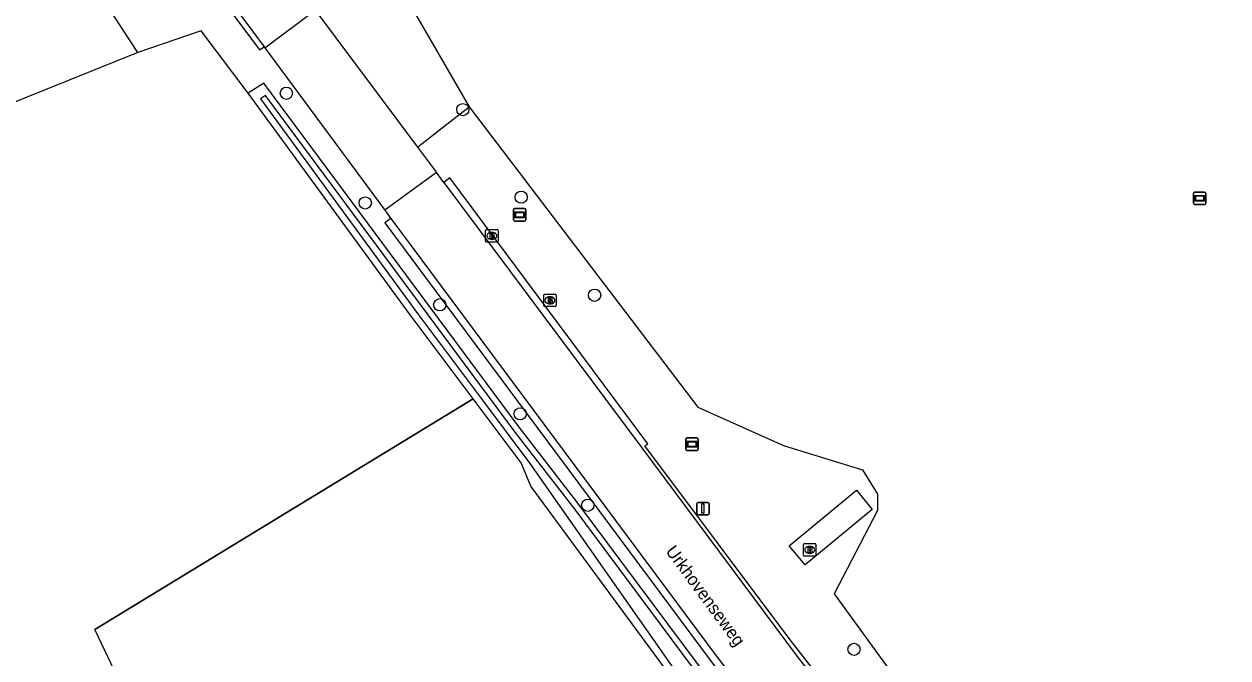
# Model space of a CAD drawing. Extents: x 164494 to 166241, y 382475 to 384494.
# Drawn here: x 165055.3 to 165151.8, y 383082.1 to 383132.9 of the extents above; entities that cross this region are included whole.
import ezdxf

# ---------------------------------------------------------------- set-up
doc = ezdxf.new("R2010")
doc.units = 0
for name, color, linetype in [('IMGEO_Berm_halfverhard', 7, 'Continuous'), ('IMGEO_Boom', 7, 'Continuous'), ('IMGEO_Bouwland', 7, 'Continuous'), ('IMGEO_Brandkraan', 7, 'Continuous'), ('IMGEO_Erf', 7, 'Continuous'), ('IMGEO_Grasland_agrarisch', 7, 'Continuous'), ('IMGEO_Grasland_overig', 7, 'Continuous'), ('IMGEO_Groenvoorziening', 7, 'Continuous'), ('IMGEO_Hek', 7, 'Continuous'), ('IMGEO_Loofbos', 7, 'Continuous'), ('IMGEO_Openbare_ruimte_label', 7, 'Continuous'), ('IMGEO_Rijbaan_lokaal_gesloten', 7, 'Continuous'), ('IMGEO_Verkeersbordpaal', 7, 'Continuous'), ('IMGEO_Verklikker', 7, 'Continuous'), ('IMGEO_Voetpad_open', 7, 'Continuous'), ('IMGEO_Waterloop', 7, 'Continuous')]:
    doc.layers.add(name, color=color, linetype=linetype)

msp = doc.modelspace()

# ---------------------------------------------------------------- linework, layer by layer
at = {"layer": 'IMGEO_Berm_halfverhard'}
for points in [[(165010.162, 383216.934), (165012.663, 383213.574), (165041.519, 383174.67), (165059.934, 383149.875), (165074.189, 383130.821), (165074.54, 383131.069)], [(165132.015, 383063.951), (165116.709, 383083.512), (165105.08, 383099.084), (165105.321, 383099.248), (165089.441, 383120.561), (165088.96, 383120.2)], [(165084.718, 383117.313), (165084.231, 383116.963), (165110.383, 383081.771), (165114.948, 383075.929), (165121.14, 383068.038), (165127.167, 383060.515), (165131.174, 383055.545)]]:
    msp.add_lwpolyline(points, dxfattribs=at)
at = {"layer": 'IMGEO_Boom'}
for centre in [(165076.331, 383127.349), (165090.474, 383126.038), (165082.657, 383118.554), (165095.156, 383119.022), (165101.044, 383111.15), (165088.626, 383110.392), (165095.079, 383101.648), (165100.493, 383094.313), (165121.84, 383082.758)]:
    msp.add_circle(centre, 0.489, dxfattribs=at)
at = {"layer": 'IMGEO_Bouwland'}
msp.add_lwpolyline([(165074.123, 383155.419), (165090.977, 383126.271)], dxfattribs=at)
at = {"layer": 'IMGEO_Brandkraan'}
for p, q in [((165092.307, 383115.49), (165092.307, 383116.342)), ((165092.382, 383116.416), (165093.234, 383116.416)), ((165092.795, 383116.196), (165092.82, 383116.196)), ((165093.308, 383116.342), (165093.308, 383115.49)), ((165093.234, 383115.416), (165092.382, 383115.416)), ((165092.818, 383115.636), (165092.793, 383115.636)), ((165097.035, 383111.246), (165097.887, 383111.246)), ((165096.96, 383110.32), (165096.96, 383111.172)), ((165097.887, 383110.246), (165097.035, 383110.246)), ((165097.471, 383110.466), (165097.446, 383110.466)), ((165097.448, 383111.026), (165097.473, 383111.026)), ((165097.961, 383111.172), (165097.961, 383110.32)), ((165117.788, 383090.307), (165117.788, 383091.159)), ((165117.863, 383091.233), (165118.715, 383091.233)), ((165118.276, 383091.013), (165118.301, 383091.013)), ((165118.789, 383091.159), (165118.789, 383090.307)), ((165118.715, 383090.233), (165117.863, 383090.233)), ((165118.299, 383090.453), (165118.274, 383090.453))]:
    msp.add_line(p, q, dxfattribs=at)
for points in [[(165092.307, 383115.49), (165092.307, 383116.342)], [(165092.382, 383116.416), (165093.234, 383116.416)], [(165092.655, 383116.116), (165092.655, 383115.716), (165092.868, 383115.716)], [(165092.886, 383116.116), (165092.655, 383116.116)], [(165092.834, 383116.035), (165092.78, 383116.035), (165092.78, 383115.959)], [(165093.308, 383116.342), (165093.308, 383115.49)], [(165093.234, 383115.416), (165092.382, 383115.416)], [(165092.78, 383115.959), (165092.833, 383115.959)], [(165092.842, 383115.883), (165092.78, 383115.883), (165092.78, 383115.802)], [(165092.78, 383115.802), (165092.842, 383115.802)], [(165097.035, 383111.246), (165097.887, 383111.246)], [(165096.96, 383110.32), (165096.96, 383111.172)], [(165097.887, 383110.246), (165097.035, 383110.246)], [(165097.308, 383110.946), (165097.308, 383110.546), (165097.521, 383110.546)], [(165097.539, 383110.946), (165097.308, 383110.946)], [(165097.487, 383110.865), (165097.433, 383110.865), (165097.433, 383110.789)], [(165097.433, 383110.789), (165097.486, 383110.789)], [(165097.495, 383110.713), (165097.433, 383110.713), (165097.433, 383110.632)], [(165097.433, 383110.632), (165097.495, 383110.632)], [(165097.961, 383111.172), (165097.961, 383110.32)], [(165117.788, 383090.307), (165117.788, 383091.159)], [(165117.863, 383091.233), (165118.715, 383091.233)], [(165118.136, 383090.933), (165118.136, 383090.533), (165118.349, 383090.533)], [(165118.367, 383090.933), (165118.136, 383090.933)], [(165118.789, 383091.159), (165118.789, 383090.307)], [(165118.715, 383090.233), (165117.863, 383090.233)], [(165118.315, 383090.852), (165118.261, 383090.852), (165118.261, 383090.776)], [(165118.261, 383090.776), (165118.314, 383090.776)], [(165118.323, 383090.7), (165118.261, 383090.7), (165118.261, 383090.619)], [(165118.261, 383090.619), (165118.323, 383090.619)]]:
    msp.add_lwpolyline(points, dxfattribs=at)
for centre, radius, start, end in [((165092.384, 383116.34), 0.0765, 91.55205, 178.44795), ((165092.384, 383116.34), 0.0765, 91.55205, 178.44795), ((165092.835, 383115.997), 0.0379, 267.82845, 90.93552), ((165092.89, 383115.971), 0.145, 59.4692, 91.53667), ((165092.915, 383116.018), 0.0922, 285.51372, 58.15012), ((165093.232, 383116.34), 0.0765, 1.55205, 88.44795), ((165093.232, 383116.34), 0.0765, 1.55205, 88.44795), ((165092.384, 383115.492), 0.0765, 181.55205, 268.44795), ((165092.384, 383115.492), 0.0765, 181.55205, 268.44795), ((165092.843, 383115.842), 0.0404, 269.87594, 90.50774), ((165092.874, 383115.967), 0.251, 268.66757, 293.53466), ((165092.92, 383115.826), 0.105, 301.31148, 78.98903), ((165093.232, 383115.492), 0.0765, 271.55205, 358.44795), ((165093.232, 383115.492), 0.0765, 271.55205, 358.44795), ((165097.037, 383111.17), 0.0765, 91.55205, 178.44795), ((165097.037, 383111.17), 0.0765, 91.55205, 178.44795), ((165097.885, 383111.17), 0.0765, 1.55205, 88.44795), ((165097.885, 383111.17), 0.0765, 1.55205, 88.44795), ((165097.037, 383110.322), 0.0765, 181.55205, 268.44795), ((165097.037, 383110.322), 0.0765, 181.55205, 268.44795), ((165097.488, 383110.827), 0.0379, 267.82845, 90.93552), ((165097.496, 383110.672), 0.0404, 269.87594, 90.50774), ((165097.527, 383110.797), 0.251, 268.66757, 293.53466), ((165097.543, 383110.801), 0.145, 59.4692, 91.53667), ((165097.568, 383110.848), 0.0922, 285.51372, 58.15012), ((165097.573, 383110.656), 0.105, 301.31148, 78.98903), ((165097.885, 383110.322), 0.0765, 271.55205, 358.44795), ((165097.885, 383110.322), 0.0765, 271.55205, 358.44795), ((165117.865, 383091.157), 0.0765, 91.55205, 178.44795), ((165117.865, 383091.157), 0.0765, 91.55205, 178.44795), ((165118.371, 383090.788), 0.145, 59.4692, 91.53667), ((165118.713, 383091.157), 0.0765, 1.55205, 88.44795), ((165118.713, 383091.157), 0.0765, 1.55205, 88.44795), ((165117.865, 383090.309), 0.0765, 181.55205, 268.44795), ((165117.865, 383090.309), 0.0765, 181.55205, 268.44795), ((165118.316, 383090.814), 0.0379, 267.82845, 90.93552), ((165118.324, 383090.659), 0.0404, 269.87594, 90.50774), ((165118.355, 383090.784), 0.251, 268.66757, 293.53466), ((165118.396, 383090.835), 0.0922, 285.51372, 58.15012), ((165118.401, 383090.643), 0.105, 301.31148, 78.98903), ((165118.713, 383090.309), 0.0765, 271.55205, 358.44795), ((165118.713, 383090.309), 0.0765, 271.55205, 358.44795)]:
    msp.add_arc(centre, radius, start, end, dxfattribs=at)
for centre, major_axis, ratio, start_param, end_param in [((165092.794, 383115.916), (-0.387, 0.002), 0.722429, 4.712389, 7.853982), ((165092.819, 383115.916), (-0.39, 0.002), 0.717154, 1.570796, 4.712389), ((165097.447, 383110.746), (-0.387, 0.002), 0.722429, 4.712389, 7.853982), ((165097.472, 383110.746), (-0.39, 0.002), 0.717154, 1.570796, 4.712389), ((165118.275, 383090.733), (-0.387, 0.002), 0.722429, 4.712389, 7.853982), ((165118.3, 383090.733), (-0.39, 0.002), 0.717154, 1.570796, 4.712389)]:
    msp.add_ellipse(centre, major_axis=major_axis, ratio=ratio, start_param=start_param, end_param=end_param, dxfattribs=at)
at = {"layer": 'IMGEO_Erf'}
msp.add_lwpolyline([(165092.654, 383033.657), (165109.176, 383042.267), (165126.099, 383051.085), (165129.346, 383052.646), (165106.891, 383080.948), (165095.917, 383095.847), (165095.148, 383097.711), (165091.308, 383102.836)], dxfattribs=at)
at = {"layer": 'IMGEO_Grasland_agrarisch'}
for points in [[(165073.256, 383127.354), (165069.489, 383132.355), (165064.424, 383130.625)], [(165091.308, 383102.836), (165086.257, 383109.578), (165073.256, 383127.354)], [(165068.089, 383069.395), (165060.973, 383084.346), (165091.308, 383102.836)]]:
    msp.add_lwpolyline(points, dxfattribs=at)
at = {"layer": 'IMGEO_Grasland_overig'}
for points in [[(165086.849, 383123.029), (165088.95, 383124.679), (165090.977, 383126.271)], [(165090.977, 383126.271), (165109.315, 383102.17), (165116.194, 383099.107), (165122.512, 383097.152), (165123.715, 383095.196), (165123.722, 383093.887), (165120.236, 383087.207), (165137.054, 383064.063), (165140.602, 383063.912), (165142.91, 383065.451), (165147.5, 383063.744), (165151.816, 383066.736)]]:
    msp.add_lwpolyline(points, dxfattribs=at)
at = {"layer": 'IMGEO_Groenvoorziening'}
msp.add_lwpolyline([(165111.774, 383078.281), (165099.629, 383094.586), (165094.904, 383100.671), (165074.525, 383128.161), (165073.256, 383127.354)], dxfattribs=at)
at = {"layer": 'IMGEO_Hek'}
for points in [[(165091.308, 383102.836), (165060.973, 383084.346)], [(165069.056, 383067.363), (165060.973, 383084.346)]]:
    msp.add_lwpolyline(points, dxfattribs=at)
at = {"layer": 'IMGEO_Loofbos'}
for points in [[(165064.424, 383130.625), (165057.111, 383141.834)], [(165064.424, 383130.625), (165017.056, 383111.524)]]:
    msp.add_lwpolyline(points, dxfattribs=at)
at = {"layer": 'IMGEO_Rijbaan_lokaal_gesloten'}
for points in [[(164958.624, 383286.837), (164967.779, 383274.687), (165004.939, 383224.601), (165007.308, 383221.332), (165010.834, 383216.638), (165074.54, 383131.069)], [(165074.593, 383130.998), (165078.641, 383134.022)], [(165078.641, 383134.022), (165086.849, 383123.029)], [(165074.54, 383131.069), (165074.593, 383130.998)], [(165074.593, 383130.998), (165084.235, 383117.963)], [(165086.849, 383123.029), (165088.367, 383120.996)], [(165088.367, 383120.996), (165084.235, 383117.963)], [(165088.96, 383120.2), (165088.367, 383120.996)], [(165088.96, 383120.2), (165104.824, 383098.91), (165117.287, 383082.185), (165131.701, 383063.704), (165135.116, 383059.491), (165138.648, 383055.401)], [(165084.235, 383117.963), (165084.718, 383117.313)], [(165084.718, 383117.313), (165110.865, 383082.129), (165115.42, 383076.3), (165121.609, 383068.413), (165127.634, 383060.891), (165131.641, 383055.922)]]:
    msp.add_lwpolyline(points, dxfattribs=at)
at = {"layer": 'IMGEO_Verkeersbordpaal'}
for p, q in [((165109.232, 383093.646), (165109.232, 383094.446)), ((165109.232, 383094.446), (165109.232, 383093.646)), ((165109.332, 383094.546), (165110.122, 383094.546)), ((165110.122, 383094.546), (165109.332, 383094.546)), ((165110.222, 383094.446), (165110.222, 383093.646)), ((165110.222, 383093.646), (165110.222, 383094.446)), ((165110.122, 383093.546), (165109.332, 383093.546)), ((165109.332, 383093.546), (165110.122, 383093.546))]:
    msp.add_line(p, q, dxfattribs=at)
msp.add_lwpolyline([(165109.652, 383094.421), (165109.802, 383094.421), (165109.802, 383093.671), (165109.652, 383093.671), (165109.652, 383094.421)], dxfattribs=at)
for centre, start, end in [((165109.332, 383094.446), 90, 180), ((165109.332, 383094.446), 90, 180), ((165110.122, 383094.446), 0, 90), ((165110.122, 383094.446), 360, 90), ((165109.332, 383093.646), 180, 270), ((165109.332, 383093.646), 180, 270), ((165110.122, 383093.646), 270, 0), ((165110.122, 383093.646), 270, 0)]:
    msp.add_arc(centre, 0.1, start, end, dxfattribs=at)
at = {"layer": 'IMGEO_Verklikker'}
for p, q in [((165149.049, 383118.532), (165149.049, 383119.332)), ((165149.049, 383119.332), (165149.049, 383118.532)), ((165149.149, 383119.432), (165149.939, 383119.432)), ((165149.939, 383119.432), (165149.149, 383119.432)), ((165150.039, 383119.332), (165150.039, 383118.532)), ((165150.039, 383118.532), (165150.039, 383119.332)), ((165094.533, 383117.206), (165094.533, 383118.006)), ((165094.533, 383118.006), (165094.533, 383117.206)), ((165094.633, 383118.106), (165095.423, 383118.106)), ((165095.423, 383118.106), (165094.633, 383118.106)), ((165095.523, 383118.006), (165095.523, 383117.206)), ((165095.523, 383117.206), (165095.523, 383118.006)), ((165149.939, 383118.432), (165149.149, 383118.432)), ((165149.149, 383118.432), (165149.939, 383118.432)), ((165095.423, 383117.106), (165094.633, 383117.106)), ((165094.633, 383117.106), (165095.423, 383117.106)), ((165108.449, 383099.709), (165109.239, 383099.709)), ((165109.239, 383099.709), (165108.449, 383099.709)), ((165108.349, 383098.809), (165108.349, 383099.609)), ((165108.349, 383099.609), (165108.349, 383098.809)), ((165109.239, 383098.709), (165108.449, 383098.709)), ((165108.449, 383098.709), (165109.239, 383098.709)), ((165109.339, 383099.609), (165109.339, 383098.809)), ((165109.339, 383098.809), (165109.339, 383099.609))]:
    msp.add_line(p, q, dxfattribs=at)
for points in [[(165149.15, 383119.164), (165149.938, 383119.164), (165149.938, 383118.7), (165149.15, 383118.7), (165149.15, 383119.164)], [(165149.215, 383119.099), (165149.215, 383118.765), (165149.873, 383118.765), (165149.873, 383119.099), (165149.215, 383119.099)], [(165094.634, 383117.838), (165095.422, 383117.838), (165095.422, 383117.374), (165094.634, 383117.374), (165094.634, 383117.838)], [(165094.699, 383117.773), (165094.699, 383117.439), (165095.357, 383117.439), (165095.357, 383117.773), (165094.699, 383117.773)], [(165108.45, 383099.441), (165109.238, 383099.441), (165109.238, 383098.977), (165108.45, 383098.977), (165108.45, 383099.441)], [(165108.515, 383099.376), (165108.515, 383099.042), (165109.173, 383099.042), (165109.173, 383099.376), (165108.515, 383099.376)]]:
    msp.add_lwpolyline(points, dxfattribs=at)
for centre, start, end in [((165149.149, 383119.332), 90, 180), ((165149.149, 383119.332), 90, 180), ((165149.939, 383119.332), 0, 90), ((165149.939, 383119.332), 360, 90), ((165094.633, 383118.006), 90, 180), ((165094.633, 383118.006), 90, 180), ((165095.423, 383118.006), 0, 90), ((165095.423, 383118.006), 360, 90), ((165149.149, 383118.532), 180, 270), ((165149.149, 383118.532), 180, 270), ((165149.939, 383118.532), 270, 0), ((165149.939, 383118.532), 270, 0), ((165094.633, 383117.206), 180, 270), ((165094.633, 383117.206), 180, 270), ((165095.423, 383117.206), 270, 0), ((165095.423, 383117.206), 270, 0), ((165108.449, 383099.609), 90, 180), ((165108.449, 383099.609), 90, 180), ((165109.239, 383099.609), 0, 90), ((165109.239, 383099.609), 360, 90), ((165108.449, 383098.809), 180, 270), ((165108.449, 383098.809), 180, 270), ((165109.239, 383098.809), 270, 0), ((165109.239, 383098.809), 270, 0)]:
    msp.add_arc(centre, 0.1, start, end, dxfattribs=at)
at = {"layer": 'IMGEO_Voetpad_open'}
msp.add_lwpolyline([(165123.299, 383093.973), (165117.916, 383089.526), (165116.654, 383091.063), (165122.029, 383095.53), (165123.299, 383093.973)], dxfattribs=at)
at = {"layer": 'IMGEO_Waterloop'}
msp.add_lwpolyline([(165111.62, 383077.665), (165099.476, 383093.969), (165094.75, 383100.055), (165074.656, 383127.161), (165074.261, 383126.911), (165086.934, 383109.584), (165091.983, 383102.844), (165095.862, 383097.667), (165107.563, 383080.96)], dxfattribs=at)

# ---------------------------------------------------------------- texts
at = {"layer": 'IMGEO_Openbare_ruimte_label'}
msp.add_text('Urkhovenseweg', height=1, rotation=306.37707, dxfattribs=at).set_placement((165106.69, 383090.619))

doc.saveas('drawing.dxf')
